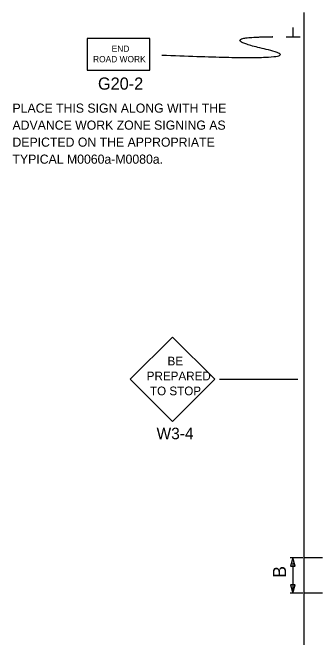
# Model space of a CAD drawing. Extents: x -1809 to 1557, y -1087 to 44.
# Drawn here: x -1714.6 to -1477.9, y -437.6 to 40.1 of the extents above; entities that cross this region are included whole.
import ezdxf

# ---------------------------------------------------------------- set-up
doc = ezdxf.new("R2010")
doc.units = 0
for name, color, linetype in [('MT_STAGE_1A_NOTES', 7, 'Continuous'), ('PAVT_EDGE_EX', 7, 'Continuous'), ('TRAFFIC_SIGNS_PR', 7, 'Continuous'), ('TYPICAL_EX', 7, 'Continuous'), ('TYPICAL_TEXT_DIMEN_PR', 7, 'Continuous')]:
    doc.layers.add(name, color=color, linetype=linetype)

msp = doc.modelspace()

# ---------------------------------------------------------------- linework, layer by layer
at = {"layer": 'MT_STAGE_1A_NOTES'}
for p, q in [((-1516.11, 21.5), (-1516.33, 21.49)), ((-1516.33, 21.49), (-1515.84, 21.49)), ((-1556.56, -240.29), (-1496.62, -240.29)), ((-1492.85, -376.78), (-1502.49, -376.78)), ((-1477.9, -376.78), (-1491.33, -376.78)), ((-1500.58, -380.59), (-1500.58, -403.77)), ((-1492.85, -403.77), (-1502.49, -403.77)), ((-1477.9, -403.77), (-1491.33, -403.77))]:
    msp.add_line(p, q, dxfattribs=at)
msp.add_open_spline([(-1600.59, 7.6), (-1478.7, 2.24), (-1563.23, 21.5), (-1516.11, 21.5)], degree=2, dxfattribs=at)
at = {"layer": 'PAVT_EDGE_EX'}
for p, q in [((-1492.05, 40.09), (-1492.05, -380.59)), ((-1492.05, -380.59), (-1492.05, -728.63))]:
    msp.add_line(p, q, dxfattribs=at)
at = {"layer": 'TRAFFIC_SIGNS_PR'}
for p, q in [((-1592.43, -208.05), (-1624.67, -240.29)), ((-1560.19, -240.29), (-1592.43, -208.05)), ((-1624.67, -240.29), (-1592.43, -272.54)), ((-1592.43, -272.54), (-1560.19, -240.29))]:
    msp.add_line(p, q, dxfattribs=at)
msp.add_lwpolyline([(-1657.65, -3.88), (-1609.65, -3.88), (-1609.65, 20.12), (-1657.65, 20.12)], close=True, dxfattribs=at)
at = {"layer": 'TYPICAL_EX'}
for p, q in [((-1500.29, 21.23), (-1500.29, 28.63)), ((-1500.29, 21.23), (-1505.63, 21.23)), ((-1494.95, 21.23), (-1500.29, 21.23)), ((-1492.05, -406.9), (-1492.05, -407))]:
    msp.add_line(p, q, dxfattribs=at)
at = {"layer": 'TYPICAL_TEXT_DIMEN_PR'}
for p, q in [((-1500.58, -376.78), (-1502.27, -383.18)), ((-1498.88, -383.18), (-1500.58, -376.78)), ((-1502.27, -383.18), (-1500.58, -383.18)), ((-1500.58, -383.18), (-1498.88, -383.18)), ((-1500.58, -397.37), (-1502.27, -397.37)), ((-1502.27, -397.37), (-1500.58, -403.77)), ((-1500.58, -403.77), (-1498.88, -397.37)), ((-1498.88, -397.37), (-1500.58, -397.37))]:
    msp.add_line(p, q, dxfattribs=at)

# ---------------------------------------------------------------- texts
at = {"layer": 'MT_STAGE_1A_NOTES'}
msp.add_text('B', height=10, rotation=90, dxfattribs=at).set_placement((-1505.72, -391.94))
at = {"layer": 'TRAFFIC_SIGNS_PR'}
for s, height, p in [('END', 4.789, (-1638.9, 10.03)), ('ROAD WORK', 4.789, (-1653.14, 2.05)), ('G20-2', 9.3, (-1649.37, -18.9)), ('PLACE THIS SIGN ALONG WITH THE', 7, (-1714.66, -36.51)), ('ADVANCE WORK ZONE SIGNING AS', 7, (-1714.66, -49.51)), ('DEPICTED ON THE APPROPRIATE', 7, (-1714.66, -62.51)), ('TYPICAL M0060a-M0080a.', 7, (-1714.66, -75.51)), ('BE', 6.65, (-1596.25, -229.69)), ('PREPARED', 6.65, (-1612.13, -241.09)), ('TO STOP', 6.65, (-1609.65, -252.49)), ('W3-4', 8.835, (-1604.63, -286.12))]:
    msp.add_text(s, height=height, dxfattribs=at).set_placement(p)

doc.saveas('drawing.dxf')
